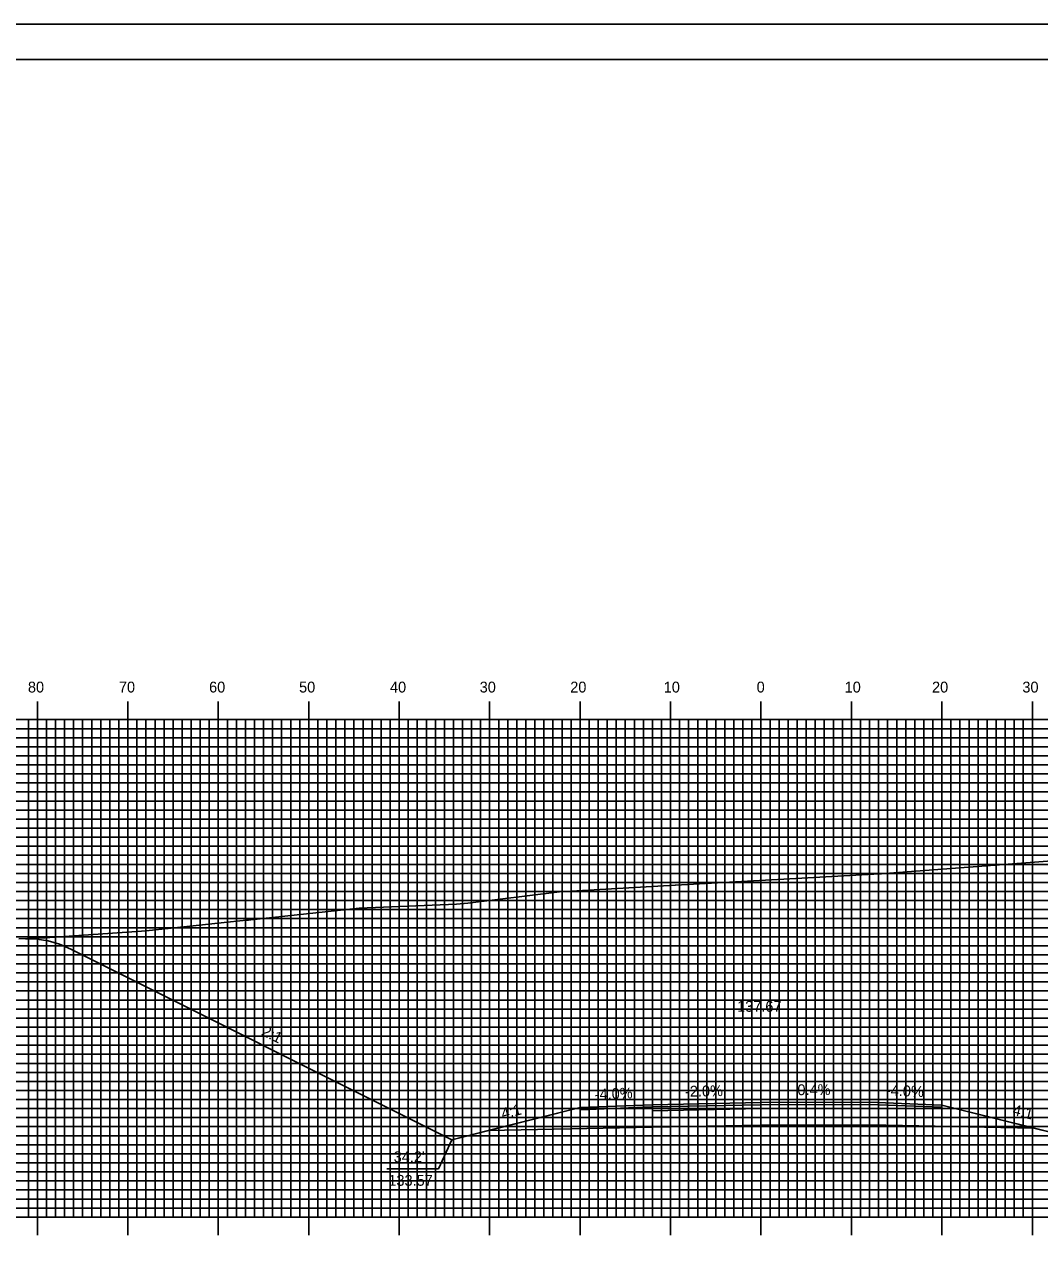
# Model space of a CAD drawing. Extents: x 1783434 to 1783777, y 442591 to 442811.
# Drawn here: x 1783518.5 to 1783630.8, y 442676.2 to 442810.5 of the extents above; entities that cross this region are included whole.
import ezdxf

# ---------------------------------------------------------------- set-up
doc = ezdxf.new("R2010")
doc.units = 0
for name, color, linetype in [('ANNOTATION', 7, 'Continuous'), ('BORDER', 7, 'Continuous'), ('D_Roadway_Centerline', 7, 'Continuous'), ('D_Roadway_Centerline_Text', 7, 'Continuous'), ('D_Roadway_Edge_Shoulder', 7, 'Continuous'), ('D_Roadway_Edge_TW', 7, 'Continuous'), ('D_Roadway_Pavement', 7, 'Continuous'), ('D_Roadway_SlopeLines', 7, 'Continuous'), ('D_Roadway_SubGrade', 7, 'Continuous'), ('H_V ANNOTATION', 7, 'Continuous'), ('MAJOR', 7, 'Continuous'), ('MINOR', 7, 'Continuous'), ('PLOT BOUNDARY', 7, 'Continuous'), ('S_Roadway_Centerline', 7, 'Continuous')]:
    doc.layers.add(name, color=color, linetype=linetype)

msp = doc.modelspace()

# ---------------------------------------------------------------- linework, layer by layer
at = {"layer": 'ANNOTATION'}
msp.add_lwpolyline([(1783558.62, 442684.01), (1783564.31, 442684.01), (1783565.8, 442687.23)], dxfattribs=at)
at = {"layer": 'BORDER'}
msp.add_lwpolyline([(1783450.37, 442596.67), (1783770.37, 442596.67), (1783770.37, 442806.67), (1783450.37, 442806.67)], close=True, dxfattribs=at)
at = {"layer": 'D_Roadway_Centerline'}
msp.add_lwpolyline([(1783518.66, 442709.45), (1783519.91, 442709.41), (1783521.16, 442709.21), (1783522.41, 442708.84), (1783523.66, 442708.3), (1783565.8, 442687.23), (1783569.8, 442688.23), (1783579.97, 442690.78), (1783587.97, 442691.1), (1783599.97, 442691.34), (1783611.97, 442691.38), (1783619.97, 442691.06), (1783630.15, 442688.52), (1783636.44, 442686.95), (1783706.93, 442722.19), (1783708.18, 442722.75), (1783709.43, 442723.18), (1783710.68, 442723.48), (1783711.93, 442723.64)], dxfattribs=at)
at = {"layer": 'D_Roadway_Edge_Shoulder'}
for points in [[(1783587.97, 442691.1), (1783579.97, 442690.78), (1783579.97, 442690.53), (1783587.97, 442690.85)], [(1783611.97, 442691.38), (1783619.97, 442691.06), (1783619.97, 442690.81), (1783611.97, 442691.13)]]:
    msp.add_lwpolyline(points, close=True, dxfattribs=at)
at = {"layer": 'D_Roadway_Edge_TW'}
msp.add_lwpolyline([(1783587.97, 442690.85), (1783587.97, 442691.1), (1783599.97, 442691.34), (1783611.97, 442691.38), (1783611.97, 442691.13), (1783599.97, 442691.09)], close=True, dxfattribs=at)
at = {"layer": 'D_Roadway_Pavement'}
msp.add_lwpolyline([(1783587.97, 442690.43), (1783587.97, 442690.85), (1783599.97, 442691.09), (1783611.97, 442691.13), (1783611.97, 442690.72), (1783599.97, 442690.67)], close=True, dxfattribs=at)
at = {"layer": 'D_Roadway_SlopeLines'}
for points in [[(1783565.8, 442687.23), (1783523.66, 442708.3), (1783522.41, 442708.84), (1783521.16, 442709.21), (1783519.91, 442709.41), (1783518.66, 442709.45)], [(1783619.97, 442691.06), (1783636.44, 442686.95)], [(1783579.97, 442690.78), (1783565.8, 442687.23)]]:
    msp.add_lwpolyline(points, dxfattribs=at)
at = {"layer": 'D_Roadway_SubGrade'}
msp.add_lwpolyline([(1783587.97, 442688.6), (1783569.8, 442688.23), (1783579.97, 442690.78), (1783579.97, 442690.53), (1783587.97, 442690.85), (1783599.97, 442691.09), (1783611.97, 442691.13), (1783619.97, 442690.81), (1783619.97, 442691.06), (1783630.15, 442688.52), (1783611.97, 442688.88), (1783599.97, 442688.84)], close=True, dxfattribs=at)
at = {"layer": 'MAJOR'}
for p, q in [((1783519.97, 442735.67), (1783519.97, 442733.67)), ((1783529.97, 442735.67), (1783529.97, 442733.67)), ((1783539.97, 442735.67), (1783539.97, 442733.67)), ((1783549.97, 442735.67), (1783549.97, 442733.67)), ((1783559.97, 442735.67), (1783559.97, 442733.67)), ((1783569.97, 442735.67), (1783569.97, 442733.67)), ((1783579.97, 442735.67), (1783579.97, 442733.67)), ((1783589.97, 442735.67), (1783589.97, 442733.67)), ((1783599.97, 442735.67), (1783599.97, 442733.67)), ((1783609.97, 442735.67), (1783609.97, 442733.67)), ((1783619.97, 442735.67), (1783619.97, 442733.67)), ((1783629.97, 442735.67), (1783629.97, 442733.67)), ((1783459.97, 442733.67), (1783739.97, 442733.67)), ((1783459.97, 442733.67), (1783739.97, 442733.67)), ((1783519.97, 442678.67), (1783519.97, 442733.67)), ((1783529.97, 442678.67), (1783529.97, 442733.67)), ((1783539.97, 442678.67), (1783539.97, 442733.67)), ((1783549.97, 442678.67), (1783549.97, 442733.67)), ((1783559.97, 442678.67), (1783559.97, 442733.67)), ((1783569.97, 442678.67), (1783569.97, 442733.67)), ((1783579.97, 442678.67), (1783579.97, 442733.67)), ((1783589.97, 442678.67), (1783589.97, 442733.67)), ((1783599.97, 442678.67), (1783599.97, 442733.67)), ((1783609.97, 442678.67), (1783609.97, 442733.67)), ((1783619.97, 442678.67), (1783619.97, 442733.67)), ((1783629.97, 442678.67), (1783629.97, 442733.67)), ((1783459.97, 442728.67), (1783739.97, 442728.67)), ((1783459.97, 442723.67), (1783739.97, 442723.67)), ((1783459.97, 442718.67), (1783739.97, 442718.67)), ((1783459.97, 442713.67), (1783739.97, 442713.67)), ((1783459.97, 442708.67), (1783739.97, 442708.67)), ((1783459.97, 442703.67), (1783739.97, 442703.67)), ((1783459.97, 442698.67), (1783739.97, 442698.67)), ((1783459.97, 442693.67), (1783739.97, 442693.67)), ((1783459.97, 442688.67), (1783739.97, 442688.67)), ((1783459.97, 442683.67), (1783739.97, 442683.67)), ((1783459.97, 442678.67), (1783739.97, 442678.67)), ((1783459.97, 442678.67), (1783739.97, 442678.67)), ((1783519.97, 442676.66), (1783519.97, 442678.67)), ((1783529.97, 442676.66), (1783529.97, 442678.67)), ((1783539.97, 442676.66), (1783539.97, 442678.67)), ((1783549.97, 442676.66), (1783549.97, 442678.67)), ((1783559.97, 442676.66), (1783559.97, 442678.67)), ((1783569.97, 442676.66), (1783569.97, 442678.67)), ((1783579.97, 442676.66), (1783579.97, 442678.67)), ((1783589.97, 442676.66), (1783589.97, 442678.67)), ((1783599.97, 442676.66), (1783599.97, 442678.67)), ((1783609.97, 442676.66), (1783609.97, 442678.67)), ((1783619.97, 442676.66), (1783619.97, 442678.67)), ((1783629.97, 442676.66), (1783629.97, 442678.67))]:
    msp.add_line(p, q, dxfattribs=at)
at = {"layer": 'MINOR'}
for p, q in [((1783459.97, 442732.67), (1783739.97, 442732.67)), ((1783518.97, 442678.67), (1783518.97, 442733.67)), ((1783520.97, 442678.67), (1783520.97, 442733.67)), ((1783521.97, 442678.67), (1783521.97, 442733.67)), ((1783522.97, 442678.67), (1783522.97, 442733.67)), ((1783523.97, 442678.67), (1783523.97, 442733.67)), ((1783524.97, 442678.67), (1783524.97, 442733.67)), ((1783525.97, 442678.67), (1783525.97, 442733.67)), ((1783526.97, 442678.67), (1783526.97, 442733.67)), ((1783527.97, 442678.67), (1783527.97, 442733.67)), ((1783528.97, 442678.67), (1783528.97, 442733.67)), ((1783530.97, 442678.67), (1783530.97, 442733.67)), ((1783531.97, 442678.67), (1783531.97, 442733.67)), ((1783532.97, 442678.67), (1783532.97, 442733.67)), ((1783533.97, 442678.67), (1783533.97, 442733.67)), ((1783534.97, 442678.67), (1783534.97, 442733.67)), ((1783535.97, 442678.67), (1783535.97, 442733.67)), ((1783536.97, 442678.67), (1783536.97, 442733.67)), ((1783537.97, 442678.67), (1783537.97, 442733.67)), ((1783538.97, 442678.67), (1783538.97, 442733.67)), ((1783540.97, 442678.67), (1783540.97, 442733.67)), ((1783541.97, 442678.67), (1783541.97, 442733.67)), ((1783542.97, 442678.67), (1783542.97, 442733.67)), ((1783543.97, 442678.67), (1783543.97, 442733.67)), ((1783544.97, 442678.67), (1783544.97, 442733.67)), ((1783545.97, 442678.67), (1783545.97, 442733.67)), ((1783546.97, 442678.67), (1783546.97, 442733.67)), ((1783547.97, 442678.67), (1783547.97, 442733.67)), ((1783548.97, 442678.67), (1783548.97, 442733.67)), ((1783550.97, 442678.67), (1783550.97, 442733.67)), ((1783551.97, 442678.67), (1783551.97, 442733.67)), ((1783552.97, 442678.67), (1783552.97, 442733.67)), ((1783553.97, 442678.67), (1783553.97, 442733.67)), ((1783554.97, 442678.67), (1783554.97, 442733.67)), ((1783555.97, 442678.67), (1783555.97, 442733.67)), ((1783556.97, 442678.67), (1783556.97, 442733.67)), ((1783557.97, 442678.67), (1783557.97, 442733.67)), ((1783558.97, 442678.67), (1783558.97, 442733.67)), ((1783560.97, 442678.67), (1783560.97, 442733.67)), ((1783561.97, 442678.67), (1783561.97, 442733.67)), ((1783562.97, 442678.67), (1783562.97, 442733.67)), ((1783563.97, 442678.67), (1783563.97, 442733.67)), ((1783564.97, 442678.67), (1783564.97, 442733.67)), ((1783565.97, 442678.67), (1783565.97, 442733.67)), ((1783566.97, 442678.67), (1783566.97, 442733.67)), ((1783567.97, 442678.67), (1783567.97, 442733.67)), ((1783568.97, 442678.67), (1783568.97, 442733.67)), ((1783570.97, 442678.67), (1783570.97, 442733.67)), ((1783571.97, 442678.67), (1783571.97, 442733.67)), ((1783572.97, 442678.67), (1783572.97, 442733.67)), ((1783573.97, 442678.67), (1783573.97, 442733.67)), ((1783574.97, 442678.67), (1783574.97, 442733.67)), ((1783575.97, 442678.67), (1783575.97, 442733.67)), ((1783576.97, 442678.67), (1783576.97, 442733.67)), ((1783577.97, 442678.67), (1783577.97, 442733.67)), ((1783578.97, 442678.67), (1783578.97, 442733.67)), ((1783580.97, 442678.67), (1783580.97, 442733.67)), ((1783581.97, 442678.67), (1783581.97, 442733.67)), ((1783582.97, 442678.67), (1783582.97, 442733.67)), ((1783583.97, 442678.67), (1783583.97, 442733.67)), ((1783584.97, 442678.67), (1783584.97, 442733.67)), ((1783585.97, 442678.67), (1783585.97, 442733.67)), ((1783586.97, 442678.67), (1783586.97, 442733.67)), ((1783587.97, 442678.67), (1783587.97, 442733.67)), ((1783588.97, 442678.67), (1783588.97, 442733.67)), ((1783590.97, 442678.67), (1783590.97, 442733.67)), ((1783591.97, 442678.67), (1783591.97, 442733.67)), ((1783592.97, 442678.67), (1783592.97, 442733.67)), ((1783593.97, 442678.67), (1783593.97, 442733.67)), ((1783594.97, 442678.67), (1783594.97, 442733.67)), ((1783595.97, 442678.67), (1783595.97, 442733.67)), ((1783596.97, 442678.67), (1783596.97, 442733.67)), ((1783597.97, 442678.67), (1783597.97, 442733.67)), ((1783598.97, 442678.67), (1783598.97, 442733.67)), ((1783600.97, 442678.67), (1783600.97, 442733.67)), ((1783601.97, 442678.67), (1783601.97, 442733.67)), ((1783602.97, 442678.67), (1783602.97, 442733.67)), ((1783603.97, 442678.67), (1783603.97, 442733.67)), ((1783604.97, 442678.67), (1783604.97, 442733.67)), ((1783605.97, 442678.67), (1783605.97, 442733.67)), ((1783606.97, 442678.67), (1783606.97, 442733.67)), ((1783607.97, 442678.67), (1783607.97, 442733.67)), ((1783608.97, 442678.67), (1783608.97, 442733.67)), ((1783610.97, 442678.67), (1783610.97, 442733.67)), ((1783611.97, 442678.67), (1783611.97, 442733.67)), ((1783612.97, 442678.67), (1783612.97, 442733.67)), ((1783613.97, 442678.67), (1783613.97, 442733.67)), ((1783614.97, 442678.67), (1783614.97, 442733.67)), ((1783615.97, 442678.67), (1783615.97, 442733.67)), ((1783616.97, 442678.67), (1783616.97, 442733.67)), ((1783617.97, 442678.67), (1783617.97, 442733.67)), ((1783618.97, 442678.67), (1783618.97, 442733.67)), ((1783620.97, 442678.67), (1783620.97, 442733.67)), ((1783621.97, 442678.67), (1783621.97, 442733.67)), ((1783622.97, 442678.67), (1783622.97, 442733.67)), ((1783623.97, 442678.67), (1783623.97, 442733.67)), ((1783624.97, 442678.67), (1783624.97, 442733.67)), ((1783625.97, 442678.67), (1783625.97, 442733.67)), ((1783626.97, 442678.67), (1783626.97, 442733.67)), ((1783627.97, 442678.67), (1783627.97, 442733.67)), ((1783628.97, 442678.67), (1783628.97, 442733.67)), ((1783459.97, 442731.67), (1783739.97, 442731.67)), ((1783459.97, 442730.67), (1783739.97, 442730.67)), ((1783459.97, 442729.67), (1783739.97, 442729.67)), ((1783459.97, 442727.67), (1783739.97, 442727.67)), ((1783459.97, 442726.67), (1783739.97, 442726.67)), ((1783459.97, 442725.67), (1783739.97, 442725.67)), ((1783459.97, 442724.67), (1783739.97, 442724.67)), ((1783459.97, 442722.67), (1783739.97, 442722.67)), ((1783459.97, 442721.67), (1783739.97, 442721.67)), ((1783459.97, 442720.67), (1783739.97, 442720.67)), ((1783459.97, 442719.67), (1783739.97, 442719.67)), ((1783459.97, 442717.67), (1783739.97, 442717.67)), ((1783459.97, 442716.67), (1783739.97, 442716.67)), ((1783459.97, 442715.67), (1783739.97, 442715.67)), ((1783459.97, 442714.67), (1783739.97, 442714.67)), ((1783459.97, 442712.67), (1783739.97, 442712.67)), ((1783459.97, 442711.67), (1783739.97, 442711.67)), ((1783459.97, 442710.67), (1783739.97, 442710.67)), ((1783459.97, 442709.67), (1783739.97, 442709.67)), ((1783459.97, 442707.67), (1783739.97, 442707.67)), ((1783459.97, 442706.67), (1783739.97, 442706.67)), ((1783459.97, 442705.67), (1783739.97, 442705.67)), ((1783459.97, 442704.67), (1783739.97, 442704.67)), ((1783459.97, 442702.67), (1783739.97, 442702.67)), ((1783459.97, 442701.67), (1783739.97, 442701.67)), ((1783459.97, 442700.67), (1783739.97, 442700.67)), ((1783459.97, 442699.67), (1783739.97, 442699.67)), ((1783459.97, 442697.67), (1783739.97, 442697.67)), ((1783459.97, 442696.67), (1783739.97, 442696.67)), ((1783459.97, 442695.67), (1783739.97, 442695.67)), ((1783459.97, 442694.67), (1783739.97, 442694.67)), ((1783459.97, 442692.67), (1783739.97, 442692.67)), ((1783459.97, 442691.67), (1783739.97, 442691.67)), ((1783459.97, 442690.67), (1783739.97, 442690.67)), ((1783459.97, 442689.67), (1783739.97, 442689.67)), ((1783459.97, 442687.67), (1783739.97, 442687.67)), ((1783459.97, 442686.67), (1783739.97, 442686.67)), ((1783459.97, 442685.67), (1783739.97, 442685.67)), ((1783459.97, 442684.67), (1783739.97, 442684.67)), ((1783459.97, 442682.67), (1783739.97, 442682.67)), ((1783459.97, 442681.67), (1783739.97, 442681.67)), ((1783459.97, 442680.67), (1783739.97, 442680.67)), ((1783459.97, 442679.67), (1783739.97, 442679.67))]:
    msp.add_line(p, q, dxfattribs=at)
at = {"layer": 'PLOT BOUNDARY'}
msp.add_lwpolyline([(1783434.19, 442590.55), (1783774.19, 442590.55), (1783774.19, 442810.55), (1783434.19, 442810.55)], close=True, dxfattribs=at)
at = {"layer": 'S_Roadway_Centerline'}
msp.add_lwpolyline([(1783517.9, 442709.42), (1783520.83, 442709.53), (1783532.01, 442710.32), (1783543.05, 442711.49), (1783543.29, 442711.51), (1783543.57, 442711.54), (1783555.54, 442712.83), (1783566.3, 442713.28), (1783567.56, 442713.38), (1783577.68, 442714.62), (1783590.47, 442715.37), (1783590.51, 442715.37), (1783613.1, 442716.63), (1783613.3, 442716.63), (1783613.5, 442716.65), (1783613.71, 442716.67), (1783629.72, 442717.89), (1783644.08, 442718.99)], dxfattribs=at)

# ---------------------------------------------------------------- texts
at = {"layer": 'ANNOTATION'}
for s, rotation, p in [('2:1', 333.4349, (1783544.66, 442698.84)), ('-4.0%', 2.2906, (1783581.61, 442691.64)), ('-2.0%', 1.1458, (1783591.58, 442691.97)), ('0.4%', 0.2256, (1783604, 442692.15)), ('-4.0%', 357.7094, (1783613.76, 442692.11)), ('4:1', 14.0362, (1783571.42, 442689.5)), ('4:1', 345.9638, (1783627.71, 442689.99))]:
    msp.add_text(s, height=1.2, rotation=rotation, dxfattribs=at).set_placement(p)
for s, p in [("34.2'", (1783559.36, 442684.73)), ('133.57', (1783558.77, 442682.13))]:
    msp.add_text(s, height=1.2, dxfattribs=at).set_placement(p)
at = {"layer": 'D_Roadway_Centerline'}
for s, p in [('C', (1783599.97, 442691.34)), ('L', (1783599.97, 442691.33))]:
    msp.add_text(s, height=0.0146, dxfattribs=at).set_placement(p)
at = {"layer": 'D_Roadway_Centerline_Text'}
msp.add_text('137.67', height=1.2, dxfattribs=at).set_placement((1783597.33, 442701.37))
at = {"layer": 'H_V ANNOTATION'}
for s, p in [('80', (1783518.92, 442736.67)), ('70', (1783528.98, 442736.67)), ('60', (1783538.95, 442736.67)), ('50', (1783548.9, 442736.67)), ('40', (1783558.95, 442736.67)), ('30', (1783568.87, 442736.67)), ('20', (1783578.88, 442736.67)), ('10', (1783589.22, 442736.67)), ('0', (1783599.49, 442736.67)), ('10', (1783609.22, 442736.67)), ('20', (1783618.88, 442736.67)), ('30', (1783628.87, 442736.67))]:
    msp.add_text(s, height=1.2, dxfattribs=at).set_placement(p)

doc.saveas('drawing.dxf')
